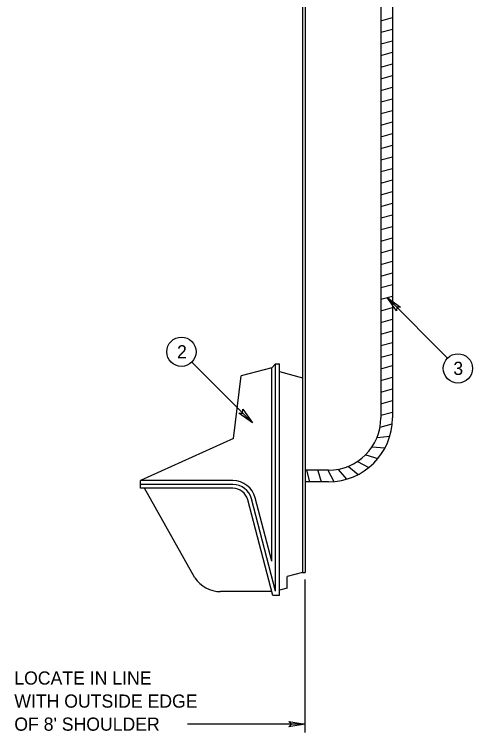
# Model space of a CAD drawing. Extents: x 99968 to 128667, y 90163 to 102182.
# Drawn here: x 126484 to 126901, y 97650 to 98304 of the extents above; entities that cross this region are included whole.
import ezdxf

# ---------------------------------------------------------------- set-up
doc = ezdxf.new("R2010")
doc.units = 0
doc.layers.add('RD Standard Plans Active', color=7, linetype='Continuous')

msp = doc.modelspace()

# ---------------------------------------------------------------- linework, layer by layer
at = {"layer": 'RD Standard Plans Active'}
for p, q in [((126745.91, 98462.31), (126745.91, 97795.57)), ((126748.53, 98459.69), (126748.53, 97795.57)), ((126817.38, 98424.87), (126817.38, 97936.31)), ((126827.84, 98424.87), (126827.84, 97936.31)), ((126817.38, 98298.16), (126827.84, 98301.08)), ((126817.38, 98287.59), (126827.84, 98290.51)), ((126817.38, 98277.02), (126827.84, 98279.94)), ((126817.38, 98266.45), (126827.84, 98269.37)), ((126817.38, 98255.88), (126827.84, 98258.8)), ((126817.38, 98245.31), (126827.84, 98248.23)), ((126817.38, 98234.74), (126827.84, 98237.66)), ((126817.38, 98224.17), (126827.84, 98227.09)), ((126817.38, 98213.6), (126827.84, 98216.52)), ((126817.38, 98203.03), (126827.84, 98205.95)), ((126817.38, 98192.46), (126827.84, 98195.38)), ((126817.38, 98181.88), (126827.84, 98184.81)), ((126817.38, 98171.31), (126827.84, 98174.23)), ((126817.38, 98160.74), (126827.84, 98163.66)), ((126817.38, 98150.17), (126827.84, 98153.09)), ((126817.38, 98139.6), (126827.84, 98142.52)), ((126817.38, 98129.03), (126827.84, 98131.95)), ((126817.38, 98118.46), (126827.84, 98121.38)), ((126817.38, 98107.89), (126827.84, 98110.81)), ((126817.38, 98097.32), (126827.84, 98100.24)), ((126817.38, 98086.75), (126827.84, 98089.67)), ((126817.38, 98076.18), (126827.84, 98079.1)), ((126817.38, 98065.61), (126827.84, 98068.53)), ((126817.38, 98055.03), (126827.84, 98057.96)), ((126817.38, 98044.46), (126827.84, 98047.39)), ((126822.95, 98046.15), (126878.05, 97990.92)), ((126817.38, 98033.89), (126827.84, 98036.81)), ((126817.38, 98023.32), (126827.84, 98026.24)), ((126817.38, 98012.75), (126827.84, 98015.67)), ((126817.38, 98002.18), (126827.84, 98005.1)), ((126817.38, 97991.61), (126827.84, 97994.53)), ((126700.4, 97931.92), (126645.3, 97987.14)), ((126721.51, 97985.57), (126718.02, 97982.08)), ((126721.51, 97778.58), (126721.51, 97985.57)), ((126721.51, 97985.57), (126725, 97985.57)), ((126725, 97774.65), (126725, 97985.57)), ((126817.38, 97981.04), (126827.84, 97983.96)), ((126718.02, 97982.08), (126690.13, 97974.61)), ((126718.02, 97805.76), (126718.02, 97982.08)), ((126725, 97978.59), (126745.91, 97972.99)), ((126683.16, 97917.58), (126690.13, 97974.61)), ((126817.38, 97970.47), (126827.84, 97973.39)), ((126817.38, 97959.9), (126827.84, 97962.82)), ((126817.38, 97949.33), (126827.84, 97952.25)), ((126817.38, 97938.76), (126827.84, 97941.68)), ((126816.65, 97927.98), (126827.6, 97931.04)), ((126683.16, 97917.58), (126598.62, 97879.24)), ((126813.92, 97918.47), (126825.44, 97919.78)), ((126809.49, 97910.06), (126821.04, 97909.04)), ((126803.49, 97902.68), (126814.61, 97899.4)), ((126787.73, 97892.2), (126796.69, 97884.85)), ((126796.13, 97896.65), (126806.38, 97891.22)), ((126769.76, 97888.68), (126748.53, 97888.68)), ((126749.52, 97888.68), (126752.44, 97878.22)), ((126760.03, 97888.57), (126763.07, 97878.14)), ((126769.14, 97888.68), (126774.53, 97878.42)), ((126778.61, 97889.51), (126785.93, 97880.52)), ((126598.62, 97872.26), (126598.62, 97879.24)), ((126682.69, 97879.24), (126598.62, 97879.24)), ((126769.76, 97878.22), (126748.53, 97878.22)), ((126682.69, 97875.75), (126598.62, 97875.75)), ((126682.69, 97875.75), (126598.62, 97875.75)), ((126682.69, 97872.26), (126598.62, 97872.26)), ((126648.1, 97790.79), (126602.11, 97872.26)), ((126718.93, 97774.65), (126696.19, 97861.84)), ((126721.51, 97778.58), (126699.56, 97862.72)), ((126718.02, 97805.76), (126702.93, 97863.6)), ((126745.91, 97795.57), (126731.97, 97791.83)), ((126745.91, 97795.57), (126748.53, 97795.57)), ((126731.97, 97781.39), (126731.97, 97791.83)), ((126748.53, 97649.68), (126748.53, 97789.18)), ((126731.97, 97781.39), (126725, 97779.52)), ((126718.02, 97778.14), (126671.46, 97778.14)), ((126725, 97774.65), (126718.93, 97774.65)), ((126748.53, 97657.42), (126641.28, 97657.42))]:
    msp.add_line(p, q, dxfattribs=at)
for points in [[(126831.69, 98033.81), (126822.95, 98046.15), (126835.27, 98037.38), (126831.83, 98037.25)], [(126691.66, 97944.26), (126700.4, 97931.92), (126688.08, 97940.68), (126691.53, 97940.81)], [(126733.62, 97659.95), (126748.53, 97657.42), (126733.62, 97654.89), (126735.96, 97657.42)]]:
    msp.add_lwpolyline(points, close=True, dxfattribs=at)
for centre in [(126635.89, 97996.58), (126887.46, 97981.48)]:
    msp.add_circle(centre, 13.33, dxfattribs=at)
for centre, radius, start, end in [((126769.76, 97936.31), 47.62, 270, 360), ((126769.76, 97936.31), 58.08, 270, 360), ((126682.69, 97858.32), 20.92, 14.62087, 90), ((126682.69, 97858.32), 17.43, 14.62087, 90), ((126682.69, 97858.32), 13.94, 14.62087, 90), ((126671.46, 97806.03), 27.89, 213.11134, 270)]:
    msp.add_arc(centre, radius, start, end, dxfattribs=at)

# ---------------------------------------------------------------- texts
for s, p in [('2', (126631.86, 97990.58)), ('3', (126883.26, 97975.48)), ('LOCATE IN LINE', (126483.8, 97693.42)), ('WITH OUTSIDE EDGE', (126483.8, 97672.42)), ("OF 8' SHOULDER ", (126483.8, 97651.42))]:
    msp.add_text(s, height=12, dxfattribs=at).set_placement(p)

doc.saveas('drawing.dxf')
